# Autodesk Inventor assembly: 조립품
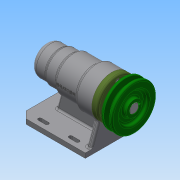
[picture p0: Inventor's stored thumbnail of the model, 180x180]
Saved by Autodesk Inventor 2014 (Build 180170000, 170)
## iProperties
Created: 2017-09
Part Number: 조립품
Document SubType Name: Assembly
Designer: user
Author: user
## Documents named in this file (12)
- C:\Users\user\Desktop\470907V1023\조립품.iam
- C:\Users\user\Desktop\470907V1023\본체.ipt
- C:\Users\user\Desktop\470907V1023\V벨트풀리.ipt
- C:\Users\user\Desktop\470907V1023\멈춤나사 M3x8.ipt
- C:\Users\user\Desktop\470907V1023\베어링 6004.ipt
- C:\Users\user\Desktop\470907V1023\베어링 51202.ipt
- C:\Users\user\Desktop\470907V1023\볼트 M4 x 12.ipt
- C:\Users\user\Desktop\470907V1023\어댑터슬리브.ipt
- C:\Users\user\Desktop\470907V1023\오일 실 20x35x7.ipt
- C:\Users\user\Desktop\470907V1023\축.ipt
- C:\Users\user\Desktop\470907V1023\커버.ipt
- C:\Users\user\Desktop\470907V1023\키 5 x 5 x 16.ipt
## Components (1 placed, 1 different names)
1. V벨트풀리:1 — 각도:2
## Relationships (1: Angle 1)
- 각도:2 [Angle]: V벨트풀리:1
